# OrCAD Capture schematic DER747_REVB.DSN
size C
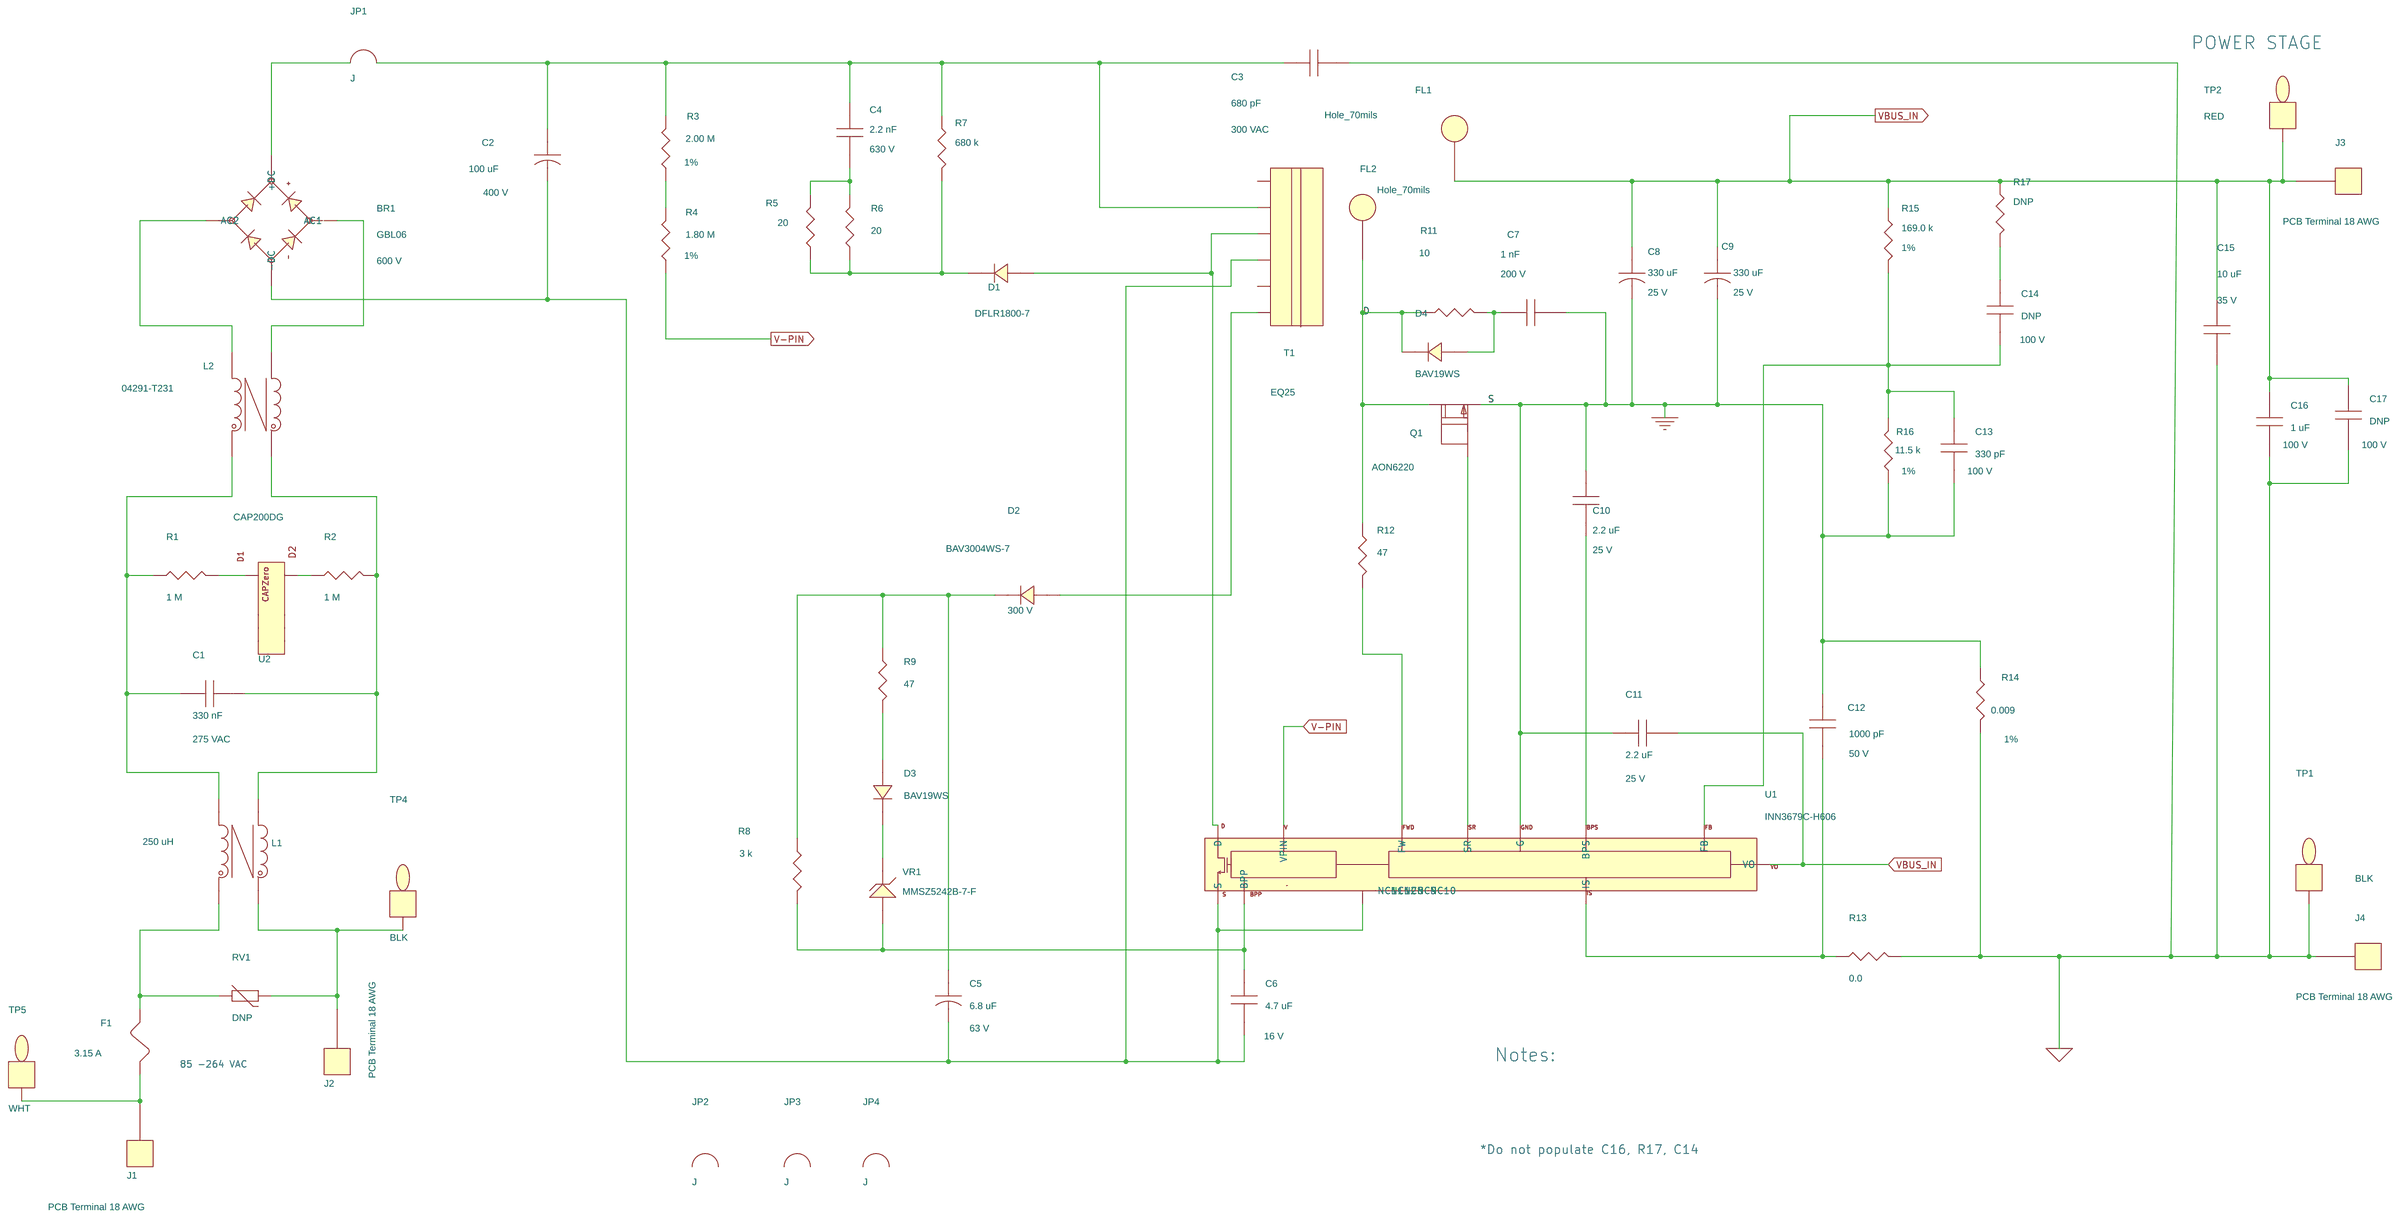
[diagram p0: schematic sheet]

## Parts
BR1  GBL06  [pidaxbridgegbl06]
C1  330 nF  [pinp_xcaprad15x8p5x14Hd040]
C2  100 uF  [pipolcapclyd630ls300040]
C3  680 pF  [pinpcaprad394x275394030]
C4  2.2 nF  [pismc1206]
C5  6.8 uF  [pipolcap4p0x11p0xls1p5d030]
C6  4.7 uF  [pismc0805]
C7  1 nF  [pismc0805]
C8  330 uF  [pipolcapcyld315ls138d030]
C9  330 uF  [pipolcapcyld315ls138d030]
C10  2.2 uF  [pismc0805]
C11  2.2 uF  [pismc1206]
C12  1000 pF  [pismr0402]
C13  330 pF  [pismc0402]
C14  DNP  [pismc0402]
C15  10 uF  [pismc0805]
C16  1 uF  [pismc0805]
C17  DNP  [pismc0805]
D1  DFLR1800-7  [pismddflr120012]
D2  BAV3004WS-7  [pismsod323]
D3  BAV19WS  [pismsod323]
D4  BAV19WS  [pismsod323]
F1  3.15 A  [pi_rst_microfuse]
FL1  Hole_70mils  [pi_hole_70mil]
FL2  Hole_70mils  [pi_hole_70mil]
J1  PCB Terminal 18 AWG  [pi_hole_18awg]
J2  PCB Terminal 18 AWG  [pi_hole_18awg]
J3  PCB Terminal 18 AWG  [pi_hole_18awg]
J4  PCB Terminal 18 AWG  [pi_hole_18awg]
JP1  J  [pi_jumper700]
JP2  J  [pi_jumper1000]
JP3  J  [pi_jumper500_d020]
JP4  J  [pi_jumper300_d020]
L1  250 uH  [pi_toroid_CMC4p_V_275uH]
L2  04291-T231  [pi_CMC_18mH_Sumida]
Q1  AON6220  [pismpqfn5x6b]
R1  1 M  [pismr1206]
R2  1 M  [pismr1206]
R3  2.00 M  [pismr1206]
R4  1.80 M  [pismr1206]
R5  20  [pismr1206]
R6  20  [pismr1206]
R7  680 k  [pismr1206]
R8  3 k  [pismr0603]
R9  47  [pismr0603]
R11  10  [pismr0805]
R12  47  [pismr0603]
R13  0.0  [pismr0402]
R14  0.009  [pismr0805]
R15  169.0 k  [pismr0402]
R16  11.5 k  [pismr0402]
R17  DNP  [pismr0402]
RV1  DNP  [pidisc350x160ls210x140040]
T1  EQ25  [pi_bobbin_eq-25_6p]
TP1  BLK  [pitpkeystone125x125]
TP2  RED  [pitpkeystone125x125]
TP4  BLK  [pitpkeystone125x125]
TP5  WHT  [pitpkeystone125x125]
U1  INN3679C-H606  [pi_ic_insop_24d]
U2  CAP200DG  [pi_ic_smd_so8_capzero]
VR1  MMSZ5242B-7-F  [pi_sm_sod-123_12]

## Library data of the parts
BR1 = DISCRETE_BRIDGE_+~~-: Disp_Voltage: 600 V; Part Number: 15-01112-00; ROOM: 1
C1 = CAP_NP: ALT_SYMBOLS: pinp_xcaprad15x8p5x14Hd040H; Disp_Voltage: 275 VAC; FPLIST: pinp_xcaprad15x8p5x14Hd040,pinp_xcaprad15x8p5x14Hd040H; Part Number: 20-09095-00; ROOM: 1; Voltage: 275 VAC
C2 = CAP_POL: ALT_SYMBOLS: pipolcapclyd630ls3000401120h; COMPGROUP: 1; Disp_Voltage: 400 V; FPLIST: pipolcapclyd630ls300040,pipolcapclyd630ls3000401120h; Part Number: 20-00517-00; ROOM: 1; Voltage: 400 V
C3 = CAP_NP: ALT_SYMBOLS: pinpycaprad500x220ls400040; COMPGROUP: 3; Disp_Voltage: 300 VAC; FPLIST: pinpcaprad394x275394030,pinpycaprad500x220ls400040; PCB Editor PCBFP: pinpycaprad540x290ls400040; Part Number: 20-09027-00; ROOM: 2; Voltage: 300 VAC
C4 = CAP_NP_0: Disp_Voltage: 630 V; Part Number: 20-08609-00; ROOM: 1; Voltage: 630 V
C5 = CAP_POL: ALT_SYMBOLS: pipolcap4p0x11p0xls1p5d030h; Disp_Voltage: 63 V; FPLIST: pipolcap4p0x11p0xls1p5d030,pipolcap4p0x11p0xls1p5d030h; Part Number: 20-09108-00; ROOM: 1; Voltage: 63 V
C6 = CAP_NP: Disp_Voltage: 16 V; Part Number: 20-08947-00; ROOM: 2; Voltage: 16 V
C7 = CAP_NP: ALT_SYMBOLS: pismc0805_1; Disp_Voltage: 200 V; FPLIST: pismc0805,pismc0805_1; PCB Editor PCBFP: pismc0603; Part Number: 20-00737-00; ROOM: 2; Voltage: 200 V
C8 C9 = CAP_POL: ALT_SYMBOLS: pipolcapcyld315ls138d030h; Disp_Voltage: 25 V; FPLIST: pipolcapcyld315ls138d030,pipolcapcyld315ls138d030h; Part Number: 20-09107-00; ROOM: 2; Voltage: 25 V
C10 = CAP_NP_0: Disp_Voltage: 25 V; Part Number: 20-08603-00; ROOM: 2; Voltage: 25 V
C11 = CAP_NP: Disp_Voltage: 25 V; Part Number: 20-01034-00; ROOM: 2; Voltage: 25 V
C12 = CAP_NP: ALT_SYMBOLS: pismr0402_1; Disp_Voltage: 50 V; FPLIST: pismr0402,pismr0402_1; Part Number: 20-09106-00; ROOM: 2; Voltage: 50 V
C13 C14 = CAP_NP: ALT_SYMBOLS: pismr0402_1; Disp_Voltage: 100 V; FPLIST: pismc0402,pismr0402_1; Part Number: 20-09059-00; ROOM: 2; Voltage: 100 V
C15 = CAP_NP: ALT_SYMBOLS: pismc0805_1; Disp_Voltage: 35 V; FPLIST: pismc0805,pismc0805_1; Part Number: 20-08720-00; ROOM: 2; Voltage: 35 V
C16 C17 = CAP_NP: Disp_Voltage: 100 V; Part Number: 20-01324-00; ROOM: 2; Voltage: 100 V
D1 = DIODE: COMPGROUP: 2; Part Number: 15-00919-00; ROOM: 1
D2 = DIODE: COMPGROUP: 1; Disp_Voltage: 300 V; Part Number: 15-01138-00; ROOM: 1
D3 = DIODE: Part Number: 15-00658-00; ROOM: 1
D4 = DIODE: Part Number: 15-00658-00; ROOM: 2
F1 = FUSE: ALT_SYMBOLS: pirstmicrofusehoz; COMPGROUP: 1; FPLIST: pi_rst_microfuse,pirstmicrofusehoz; Part Number: 40-00020-00; ROOM: 1
FL1 FL2 = FlyingLead: Part Number: 35-00282-00; ROOM: 2
J1 J2 = TERM_1Pin: Part Number: 35-00007-00; ROOM: 1
J3 J4 = TERM_1Pin: Part Number: 35-00007-00; ROOM: 2
JP1 = JUMPER_1: Part Number: 65-00124-00
JP2 = JUMPER_1: Part Number: 65-00127-00
JP3 = JUMPER_1: Part Number: 65-00600-03
JP4 = JUMPER_1: Part Number: 65-00600-01
L1 = TORRID_4P_12_34: ALT_SYMBOLS: pi_toroid_CMC4p_V,pi_toroid_CMC4p_V_275uH; FPLIST: pi_toroid_CMC4p_H,pi_toroid_CMC4p_V,pi_toroid_CMC4p_V_275uH; Part Number: 32-00347-00; ROOM: 1
L2 = TORRID_4P_12_43a: Part Number: 30-00462-00; ROOM: 1
Q1 = FET_N_SGD_123_4_5678: Part Number: 50-00276-00; ROOM: 2
R1 R2 = R: Part Number: 05-01424-00; ROOM: 1
R3 = R: Disp_Tol: 1%; Part Number: 05-03156-00; ROOM: 1
R4 = R: Disp_Tol: 1%; Part Number: 05-03155-00; ROOM: 1
R5 R6 = R: Part Number: 05-01311-00; ROOM: 1
R7 = R: Part Number: 05-01420-00; ROOM: 1
R8 = R: Part Number: 05-01699-00; ROOM: 1
R9 = R: Part Number: 05-01656-00; ROOM: 1
R11 = R: Part Number: 05-01471-00; ROOM: 2
R12 = R: Part Number: 05-01656-00; ROOM: 2
R13 = R: Part Number: 05-06420-00; ROOM: 2
R14 = R: Disp_Tol: 1%; Part Number: 05-06508-00
R15 = R: Disp_Tol: 1%; Part Number: 05-06060-00; ROOM: 2
R16 = R: Disp_Tol: 1%; Part Number: 05-05941-00; ROOM: 2
R17 = R: ALT_SYMBOLS: pismr0402_1; FPLIST: pismr0402,pismr0402_1; Part Number: 05-03420-00; ROOM: 2
RV1 = VARISTOR: ALT_SYMBOLS: pi_disc_354x220_ls220x10_040_h; FPLIST: pidisc350x160ls210x140040,pi_disc_354x220_ls220x10_040_h; Part Number: 85-00015-00; ROOM: 1
T1 = BEQ2506_6P: Part Number: 25-01136-00
TP1 TP4 = TESTPOINT: Part Number: 35-00042-00
TP2 = TESTPOINT: Part Number: 35-00043-00
TP5 = TESTPOINT: Part Number: 35-00044-00
U1 = Inno3EP_0: Part Number: 10-01050-03
U2 = CAPZero: Part Number: 10-00958-00; ROOM: 1
VR1 = DIODE_ZENER: Part Number: 15-01090-00; ROOM: 1

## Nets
GND: C7.2 C8.2 C9.2 C10.1 C11.1 C12.1 C13.2 Q1.1(S) R14.1 R16.1 U1.2(G)
GND_SIGNAL: C3.2 C15.2 C16.2 C17.2 J4.1 R13.2 R14.2 TP1.1
VBUS_IN: C8.1 C9.1 C11.2 C15.1 C16.1 C17.1 FL1.1 J3.1 R15.1 R17.1 TP2.1 U1.6(VO)
D: D4.1 FL2.1 Q1.5(D) R11.2 R12.1
NC8: U1.8(NC8)
NC9: U1.9(NC9)
NC10: U1.10(NC10)
NC11: U1.11(NC11)
NC12: U1.12(NC12)
V-PIN: R4.1 U1.13(VPIN)
N10479111: F1.1 J1.1 TP5.1
N10805923: BR1.4(-DC) C2.2 C5.2 C6.2 T1.4 U1.15 U1.16(S)
N10806149: C6.1 R8.2 U1.14(BPP) VR1.2
N10808843: C12.2 R13.1 U1.1(IS)
N10809540: Q1.4(G) U1.5(SR)
N10813018: R3.1 R4.2
N10840366: C2.1 C3.1 C4.1 JP1.2 R3.2 R7.1 T1.2
N10873526: R12.2 U1.7(FW)
N10897256: C13.1 C14.2 R15.2 R16.2 U1.3(FB)
N10950053: C5.1 D2.1 R8.1 R9.1
N10966650: D1.2 T1.3 U1.24(D)
N11058959: BR1.1(+DC) JP1.1
N11077448: D3.2 R9.2
N11099981: C1.1 L1.2 L2.1 R1.1
N11100013: C1.2 L1.4 L2.4 R2.2
N11100021: BR1.3(AC2) L2.2
N11100037: BR1.2(AC1) L2.3
N11105885: D2.2 T1.6
N11139529: D1.1 R5.1 R6.1 R7.2
N11139619: C4.2 R5.2 R6.2
N11156493: C7.1 D4.2 R11.1
N11376588: F1.2 L1.1 RV1.1
N11376604: J2.1 L1.3 RV1.2 TP4.1
N11381159: R1.2 U2.2(D1)
N11473834: D3.1 VR1.1
N11479585: C14.1 R17.2
N11508957: R2.1 U2.7(D2)
N11512145: C10.2 U1.4(BPS)

Not connected (* = marked no-connect by the designer): JP2 1 2; JP3 1 2; JP4 1 2; Q1 2(S2) 3(S3) 6(D6) 7(D7) 8(D8); T1 1 5; U2 1(NC1) 3(NC2) 4(NC3) 5(NC4) 6(NC5) 8(NC8)

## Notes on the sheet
- POWER STAGE
- Notes:
- 85 -264 VAC
- *Do not populate C16, R17, C14
